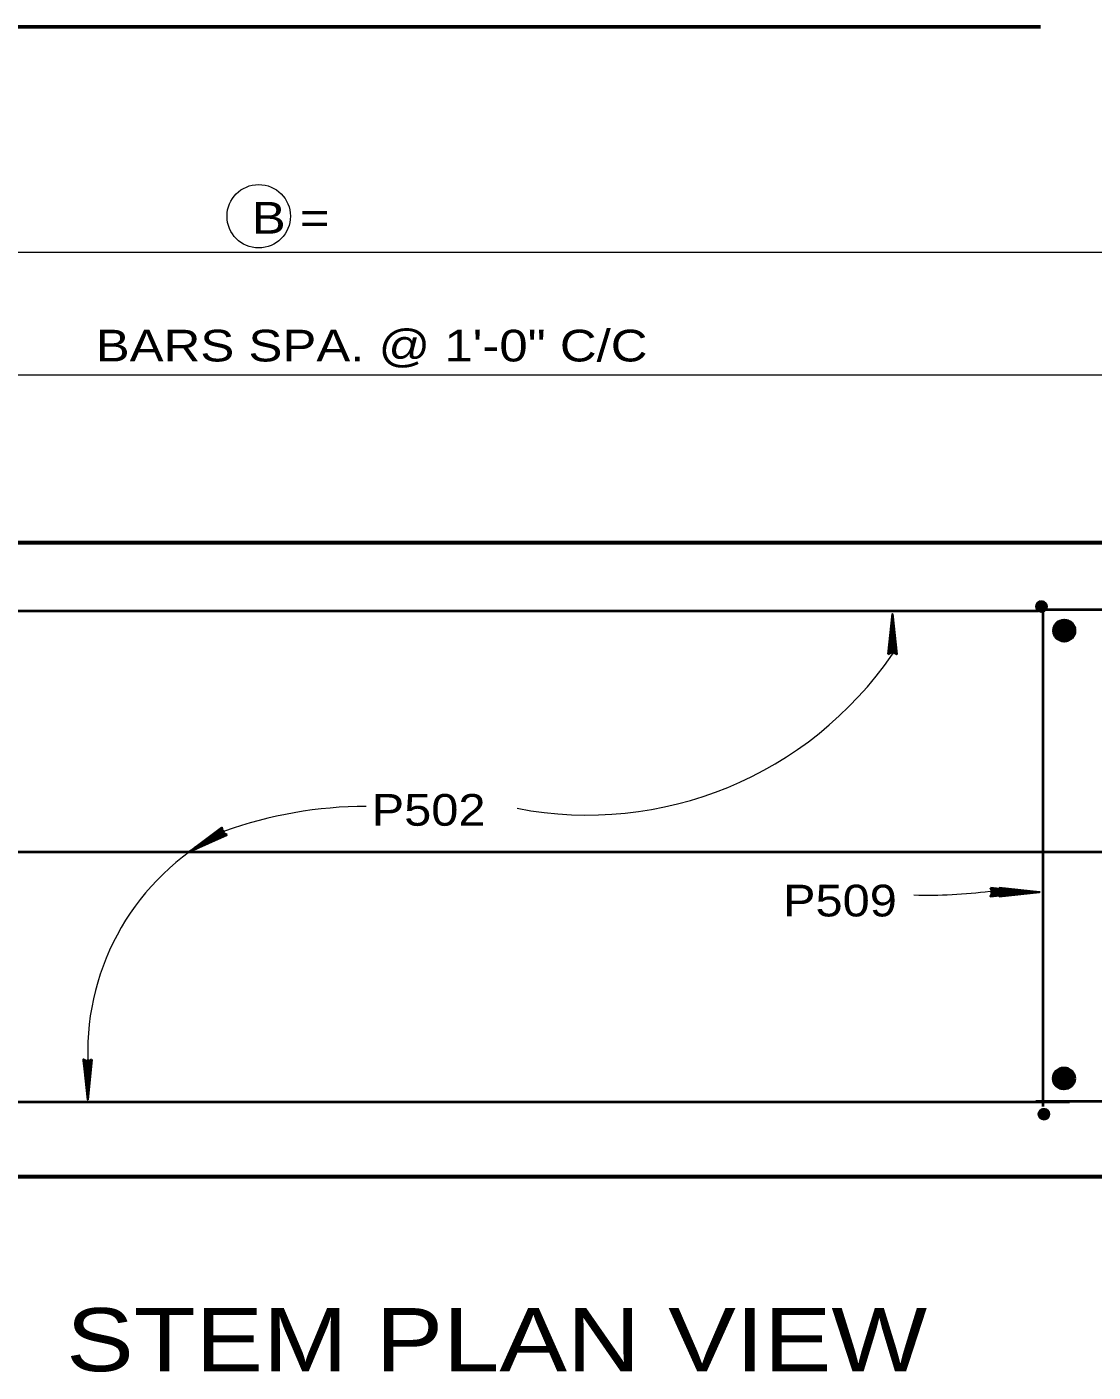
# Model space of a CAD drawing. Extents: x 4.49 to 7.69, y 0.28 to 2.27.
# Drawn here: x 5.0493 to 5.3295, y 1.2601 to 1.6136 of the extents above; entities that cross this region are included whole.
import ezdxf

# ---------------------------------------------------------------- set-up
doc = ezdxf.new("R2010")
doc.units = 0
doc.header["$LTSCALE"] = 0.0033
doc.layers.add('1', color=7, linetype='Continuous', lineweight=35)

msp = doc.modelspace()

# ---------------------------------------------------------------- linework, layer by layer
at = {"layer": '1', "lineweight": 53}
msp.add_line((5.043, 1.613583), (5.315667, 1.613583), dxfattribs=at)
at = {"layer": '1', "lineweight": 13}
for p, q in [((4.87325, 1.554417), (5.455583, 1.554417)), ((4.89, 1.522167), (5.436917, 1.522167))]:
    msp.add_line(p, q, dxfattribs=at)
at = {"layer": '1', "lineweight": 60}
for p, q in [((4.873333, 1.478083), (5.456667, 1.478083)), ((5.321667, 1.456417), (5.321833, 1.4535)), ((5.321833, 1.456417), (5.322083, 1.4535)), ((5.322083, 1.456417), (5.32225, 1.4535)), ((5.32225, 1.456417), (5.322417, 1.4535)), ((5.322417, 1.456417), (5.322583, 1.4535)), ((5.3225, 1.4565), (5.32275, 1.4535)), ((5.32275, 1.4565), (5.322917, 1.4535)), ((5.323, 1.4565), (5.323167, 1.4535)), ((5.323167, 1.4565), (5.323417, 1.4535)), ((5.323333, 1.4565), (5.3235, 1.4535)), ((5.3235, 1.4565), (5.32375, 1.453583)), ((5.32375, 1.4565), (5.323917, 1.453583)), ((5.319417, 1.454333), (5.319583, 1.456167)), ((5.319417, 1.454333), (5.324167, 1.453583)), ((5.319667, 1.45625), (5.319833, 1.453333)), ((5.319917, 1.45625), (5.320083, 1.453333)), ((5.320083, 1.45625), (5.320333, 1.453333)), ((5.32025, 1.45625), (5.320417, 1.453333)), ((5.320417, 1.45625), (5.320667, 1.453333)), ((5.320667, 1.456333), (5.320833, 1.453417)), ((5.32075, 1.456333), (5.320917, 1.453417)), ((5.320917, 1.456333), (5.321083, 1.453417)), ((5.321, 1.456333), (5.321167, 1.453417)), ((5.321167, 1.456333), (5.321417, 1.453417)), ((5.321417, 1.456333), (5.321667, 1.453417)), ((5.319333, 1.336667), (5.3195, 1.3385)), ((5.319333, 1.336667), (5.324083, 1.335917)), ((5.319583, 1.338583), (5.31975, 1.335667)), ((5.319833, 1.338583), (5.32, 1.335667)), ((5.32, 1.338583), (5.32025, 1.335667)), ((5.320167, 1.338583), (5.320333, 1.335667)), ((5.320333, 1.338583), (5.320583, 1.335667)), ((5.320583, 1.338667), (5.32075, 1.33575)), ((5.320667, 1.338667), (5.320833, 1.33575)), ((5.320833, 1.338667), (5.321, 1.33575)), ((5.320917, 1.338667), (5.321083, 1.33575)), ((5.321083, 1.338667), (5.321333, 1.33575)), ((5.321333, 1.338667), (5.321583, 1.33575)), ((5.321583, 1.33875), (5.32175, 1.335833)), ((5.32175, 1.33875), (5.322, 1.335833)), ((5.322, 1.33875), (5.322167, 1.335833)), ((5.322167, 1.33875), (5.322333, 1.335833)), ((5.322333, 1.33875), (5.3225, 1.335833)), ((5.322417, 1.338833), (5.322667, 1.335833)), ((5.322667, 1.338833), (5.322833, 1.335833)), ((5.322917, 1.338833), (5.323083, 1.335833)), ((5.323083, 1.338833), (5.323333, 1.335833)), ((5.32325, 1.338833), (5.323417, 1.335833)), ((5.323417, 1.338833), (5.323667, 1.335917)), ((5.323667, 1.338833), (5.323833, 1.335917))]:
    msp.add_line(p, q, dxfattribs=at)
at = {"layer": '1', "lineweight": 40}
for p, q in [((5.31475, 1.460667), (5.31675, 1.460333)), ((5.314833, 1.461167), (5.316833, 1.46075)), ((5.314833, 1.460917), (5.316833, 1.460583)), ((5.314833, 1.460833), (5.31675, 1.4605)), ((5.314833, 1.46075), (5.31675, 1.460417)), ((5.315, 1.462083), (5.314917, 1.460583)), ((5.314917, 1.461583), (5.316917, 1.46125)), ((5.314917, 1.4615), (5.316917, 1.461083)), ((5.314917, 1.461417), (5.316833, 1.461)), ((5.314917, 1.461333), (5.316833, 1.460917)), ((5.315083, 1.462083), (5.315, 1.460583)), ((5.315, 1.462083), (5.317, 1.46175)), ((5.315, 1.462), (5.317, 1.461667)), ((5.315, 1.461917), (5.317, 1.4615)), ((5.315, 1.461833), (5.317, 1.461417)), ((5.315, 1.461667), (5.316917, 1.461333)), ((5.315083, 1.46225), (5.317, 1.461917)), ((5.315167, 1.462083), (5.315083, 1.460583)), ((5.31525, 1.462083), (5.315167, 1.460583)), ((5.315167, 1.4605), (5.382333, 1.4605)), ((5.315333, 1.462083), (5.31525, 1.460583)), ((5.3155, 1.462083), (5.315417, 1.460583)), ((5.315583, 1.462083), (5.3155, 1.460583)), ((5.315667, 1.462083), (5.315583, 1.460583)), ((5.31575, 1.462083), (5.315667, 1.460583)), ((5.315833, 1.462083), (5.31575, 1.460583)), ((5.315917, 1.462083), (5.315833, 1.460583)), ((5.316, 1.462083), (5.315917, 1.460583)), ((5.316167, 1.462), (5.316, 1.4605)), ((5.316333, 1.462), (5.316167, 1.4605)), ((5.31625, 1.46125), (5.31625, 1.329917)), ((5.316417, 1.462), (5.316333, 1.4605)), ((5.316417, 1.462), (5.316333, 1.4605)), ((5.3165, 1.462), (5.316417, 1.4605)), ((5.316583, 1.462), (5.3165, 1.4605)), ((5.316667, 1.462), (5.316583, 1.4605)), ((5.31675, 1.462), (5.316667, 1.4605)), ((5.316833, 1.462), (5.31675, 1.4605)), ((5.316917, 1.462), (5.316833, 1.4605)), ((5.317083, 1.462), (5.317, 1.4605)), ((5.324, 1.4565), (5.319417, 1.454333)), ((5.319583, 1.456167), (5.320833, 1.457333)), ((5.323583, 1.456833), (5.31975, 1.456167)), ((5.323667, 1.4565), (5.31975, 1.455833)), ((5.321667, 1.456), (5.320333, 1.457)), ((5.323667, 1.456333), (5.31975, 1.455583)), ((5.32375, 1.456083), (5.319833, 1.455333)), ((5.32375, 1.455917), (5.319833, 1.455167)), ((5.319833, 1.453333), (5.323583, 1.452917)), ((5.32375, 1.455667), (5.319917, 1.454917)), ((5.323833, 1.4555), (5.32, 1.454833)), ((5.323833, 1.455333), (5.32, 1.454583)), ((5.323917, 1.455083), (5.320083, 1.454333)), ((5.323917, 1.454917), (5.320083, 1.454167)), ((5.324, 1.454667), (5.320083, 1.453917)), ((5.324083, 1.45425), (5.320167, 1.4535)), ((5.324083, 1.454083), (5.32025, 1.453333)), ((5.324083, 1.453833), (5.32025, 1.453167)), ((5.324167, 1.45375), (5.320333, 1.453)), ((5.324167, 1.453583), (5.320333, 1.452833)), ((5.323917, 1.338833), (5.319333, 1.336667)), ((5.3195, 1.3385), (5.32075, 1.339667)), ((5.3235, 1.339167), (5.319667, 1.3385)), ((5.323583, 1.338833), (5.319667, 1.338167)), ((5.323583, 1.338667), (5.319667, 1.337917)), ((5.323667, 1.338417), (5.31975, 1.337667)), ((5.323667, 1.33825), (5.31975, 1.3375)), ((5.323667, 1.338), (5.319833, 1.33725)), ((5.32375, 1.337833), (5.319917, 1.337167)), ((5.32375, 1.337667), (5.319917, 1.336917)), ((5.323833, 1.337417), (5.32, 1.336667)), ((5.323833, 1.33725), (5.32, 1.3365)), ((5.323917, 1.337), (5.32, 1.33625)), ((5.324, 1.336583), (5.320083, 1.335833)), ((5.324, 1.336417), (5.320167, 1.335667)), ((5.321583, 1.338333), (5.32025, 1.339333)), ((5.31975, 1.335667), (5.3235, 1.33525)), ((5.324, 1.336167), (5.320167, 1.3355)), ((5.324083, 1.336083), (5.32025, 1.335333)), ((5.324083, 1.335917), (5.32025, 1.335167)), ((5.314417, 1.33125), (5.382333, 1.33125)), ((5.315417, 1.32725), (5.317417, 1.326917)), ((5.3155, 1.32775), (5.3175, 1.327333)), ((5.3155, 1.3275), (5.3175, 1.327167)), ((5.3155, 1.327417), (5.317417, 1.327083)), ((5.3155, 1.327333), (5.317417, 1.327)), ((5.315667, 1.328667), (5.315583, 1.327167)), ((5.315583, 1.328167), (5.317583, 1.327833)), ((5.315583, 1.328083), (5.317583, 1.327667)), ((5.315583, 1.328), (5.3175, 1.327583)), ((5.315583, 1.327917), (5.3175, 1.3275)), ((5.31575, 1.328667), (5.315667, 1.327167)), ((5.315667, 1.328667), (5.317667, 1.328333)), ((5.315667, 1.328583), (5.317667, 1.32825)), ((5.315667, 1.3285), (5.317667, 1.328083)), ((5.315667, 1.328417), (5.317667, 1.328)), ((5.315667, 1.32825), (5.317583, 1.327917)), ((5.31575, 1.328833), (5.317667, 1.3285)), ((5.315833, 1.328667), (5.31575, 1.327167)), ((5.315917, 1.328667), (5.315833, 1.327167)), ((5.316, 1.328667), (5.315917, 1.327167)), ((5.316167, 1.328667), (5.316083, 1.327167)), ((5.31625, 1.328667), (5.316167, 1.327167)), ((5.316333, 1.328667), (5.31625, 1.327167)), ((5.316417, 1.328667), (5.316333, 1.327167)), ((5.3165, 1.328667), (5.316417, 1.327167)), ((5.316583, 1.328667), (5.3165, 1.327167)), ((5.316667, 1.328667), (5.316583, 1.327167)), ((5.316833, 1.328583), (5.316667, 1.327083)), ((5.317, 1.328583), (5.316833, 1.327083)), ((5.317083, 1.328583), (5.317, 1.327083)), ((5.317083, 1.328583), (5.317, 1.327083)), ((5.317167, 1.328583), (5.317083, 1.327083)), ((5.31725, 1.328583), (5.317167, 1.327083)), ((5.317333, 1.328583), (5.31725, 1.327083)), ((5.317417, 1.328583), (5.317333, 1.327083)), ((5.3175, 1.328583), (5.317417, 1.327083)), ((5.317583, 1.328583), (5.3175, 1.327083)), ((5.31775, 1.328583), (5.317667, 1.327083))]:
    msp.add_line(p, q, dxfattribs=at)
at = {"layer": '1'}
for p, q in [((5.27575, 1.449), (5.276667, 1.456833)), ((5.27575, 1.449), (5.276667, 1.456833)), ((5.275833, 1.449), (5.276667, 1.456833)), ((5.275917, 1.449), (5.27675, 1.456833)), ((5.275917, 1.449), (5.276917, 1.456833)), ((5.27675, 1.44875), (5.27675, 1.459333)), ((5.277417, 1.448917), (5.276667, 1.45625)), ((5.277583, 1.449), (5.27675, 1.456333)), ((5.277667, 1.449), (5.276917, 1.456333)), ((5.277833, 1.449), (5.277, 1.456333)), ((5.10125, 1.40225), (5.092167, 1.396917)), ((5.101417, 1.4015), (5.09425, 1.398083)), ((5.101417, 1.4015), (5.09425, 1.398333)), ((5.1015, 1.401417), (5.09425, 1.398083)), ((5.101667, 1.401167), (5.09425, 1.398083)), ((5.101667, 1.401167), (5.09425, 1.398083)), ((5.100583, 1.402917), (5.094583, 1.3985)), ((5.1005, 1.402917), (5.094667, 1.398667)), ((5.10075, 1.402917), (5.094833, 1.398417)), ((5.100917, 1.402667), (5.094833, 1.398417)), ((5.3025, 1.38625), (5.313083, 1.38625)), ((5.302667, 1.385583), (5.31, 1.386333)), ((5.30275, 1.38725), (5.310583, 1.386333)), ((5.30275, 1.38725), (5.310583, 1.386333)), ((5.30275, 1.387167), (5.310583, 1.386333)), ((5.30275, 1.387083), (5.310583, 1.38625)), ((5.30275, 1.387083), (5.310583, 1.386083)), ((5.30275, 1.385417), (5.310083, 1.38625)), ((5.30275, 1.385333), (5.310083, 1.386083)), ((5.30275, 1.385167), (5.310083, 1.386)), ((5.304833, 1.38625), (5.315417, 1.38625)), ((5.305, 1.385583), (5.312333, 1.386333)), ((5.305083, 1.38725), (5.312917, 1.386333)), ((5.305083, 1.38725), (5.312917, 1.386333)), ((5.305083, 1.387167), (5.312917, 1.386333)), ((5.305083, 1.387083), (5.312917, 1.38625)), ((5.305083, 1.387083), (5.312917, 1.386083)), ((5.305083, 1.385417), (5.312417, 1.38625)), ((5.305083, 1.385333), (5.312417, 1.386083)), ((5.305083, 1.385167), (5.312417, 1.386)), ((5.06425, 1.342), (5.065083, 1.334667)), ((5.064417, 1.342), (5.065167, 1.334667)), ((5.0645, 1.342), (5.065333, 1.334667)), ((5.064667, 1.342083), (5.065417, 1.33475)), ((5.066167, 1.342), (5.065167, 1.334167)), ((5.065333, 1.34225), (5.065333, 1.331667)), ((5.066167, 1.342), (5.065333, 1.334167)), ((5.066333, 1.342), (5.065417, 1.334167)), ((5.066333, 1.342), (5.065417, 1.334167)), ((5.06625, 1.342), (5.065417, 1.334167))]:
    msp.add_line(p, q, dxfattribs=at)
at = {"layer": '1', "lineweight": 60}
for points in [[(5.456667, 1.478083), (5.456667, 1.311417), (4.873333, 1.311417), (4.873333, 1.478083)], [(5.324583, 1.454833), (5.319417, 1.4555), (5.324, 1.4565)], [(5.320333, 1.452833), (5.320333, 1.457), (5.322, 1.452333), (5.3215, 1.4575), (5.323583, 1.452917), (5.322833, 1.457417), (5.32125, 1.452417), (5.324417, 1.45575), (5.319583, 1.456167), (5.322833, 1.4525), (5.320833, 1.457333), (5.324, 1.4565), (5.324167, 1.453583)], [(5.320833, 1.457333), (5.322083, 1.455167), (5.319833, 1.453333)], [(5.323583, 1.452917), (5.322083, 1.455167), (5.32425, 1.456083), (5.32225, 1.4575), (5.322083, 1.45525), (5.320417, 1.452917), (5.324417, 1.45525), (5.321667, 1.456)], [(5.32025, 1.335167), (5.32025, 1.339333), (5.321917, 1.334667), (5.321417, 1.339833), (5.3235, 1.33525), (5.32275, 1.33975), (5.321167, 1.33475), (5.324333, 1.338083), (5.3195, 1.3385), (5.32275, 1.334833), (5.32075, 1.339667), (5.323917, 1.338833), (5.324083, 1.335917)], [(5.3235, 1.33525), (5.322, 1.3375), (5.324167, 1.338417), (5.322167, 1.339833), (5.322, 1.337583), (5.320333, 1.33525), (5.324333, 1.337583), (5.321583, 1.338333)], [(5.3245, 1.337167), (5.319333, 1.337833), (5.323917, 1.338833)], [(5.32075, 1.339667), (5.322, 1.3375), (5.31975, 1.335667)]]:
    msp.add_lwpolyline(points, dxfattribs=at)
at = {"layer": '1', "lineweight": 40}
for points in [[(4.94275, 1.456), (4.95, 1.460167), (5.315167, 1.460167)], [(5.314583, 1.46125), (5.317167, 1.461583), (5.314833, 1.462083), (5.317167, 1.461), (5.31475, 1.460583), (5.31675, 1.46025), (5.31675, 1.462333), (5.315833, 1.46), (5.316083, 1.462583), (5.315083, 1.46025), (5.315417, 1.462583), (5.31625, 1.46), (5.314667, 1.46175), (5.317083, 1.461917), (5.315417, 1.460083), (5.3165, 1.4625), (5.314833, 1.462083), (5.31475, 1.460583), (5.315833, 1.46), (5.31675, 1.46025), (5.317167, 1.461), (5.317083, 1.461917), (5.3165, 1.4625), (5.315833, 1.461417), (5.317, 1.4605), (5.315083, 1.46025), (5.315833, 1.461417), (5.31475, 1.461917), (5.31575, 1.462583), (5.315833, 1.4615), (5.316667, 1.46025), (5.314667, 1.4615), (5.316, 1.461833), (5.31675, 1.462333)], [(5.324167, 1.453583), (5.322083, 1.452333), (5.320333, 1.452833), (5.319417, 1.454333)], [(4.893667, 1.396833), (5.314, 1.396833), (5.435333, 1.396833)], [(5.324083, 1.335917), (5.322, 1.334667), (5.32025, 1.335167), (5.319333, 1.336667)], [(4.894417, 1.33525), (4.941917, 1.33525), (4.949167, 1.331083), (5.323333, 1.331083)], [(5.31525, 1.327833), (5.317833, 1.328167), (5.3155, 1.328667), (5.317833, 1.327583), (5.315417, 1.327167), (5.317417, 1.326833), (5.317417, 1.328917), (5.3165, 1.326583), (5.31675, 1.329167), (5.31575, 1.326833), (5.316083, 1.329167), (5.316917, 1.326583), (5.315333, 1.328333), (5.31775, 1.3285), (5.316083, 1.326667), (5.317167, 1.329083), (5.3155, 1.328667), (5.315417, 1.327167), (5.3165, 1.326583), (5.317417, 1.326833), (5.317833, 1.327583), (5.31775, 1.3285), (5.317167, 1.329083), (5.3165, 1.328), (5.317667, 1.327083), (5.31575, 1.326833), (5.3165, 1.328), (5.315417, 1.3285), (5.316417, 1.329167), (5.3165, 1.328083), (5.317333, 1.326833), (5.315333, 1.328083), (5.316667, 1.328417), (5.317417, 1.328917)]]:
    msp.add_lwpolyline(points, dxfattribs=at)
at = {"layer": '1'}
for points in [[(5.275667, 1.44875), (5.27675, 1.459333), (5.277917, 1.44875), (5.27675, 1.449333)], [(5.276667, 1.4495), (5.276583, 1.454167), (5.276667, 1.454167), (5.276667, 1.45325), (5.276583, 1.4495), (5.2765, 1.4525), (5.276417, 1.449333), (5.276333, 1.451583), (5.27625, 1.449333), (5.2765, 1.452833), (5.276667, 1.4575), (5.276917, 1.456583), (5.276917, 1.457833), (5.276917, 1.4495), (5.277083, 1.451917), (5.277083, 1.449333), (5.276667, 1.454667), (5.277333, 1.449333)], [(5.101917, 1.40125), (5.092167, 1.396917), (5.100583, 1.403167), (5.100833, 1.401833)], [(5.10075, 1.401667), (5.096667, 1.399333), (5.096583, 1.399333), (5.0975, 1.399833), (5.100667, 1.401583), (5.098167, 1.400083), (5.100833, 1.401583), (5.099, 1.400333), (5.101083, 1.401333), (5.097917, 1.4), (5.093833, 1.397583), (5.094417, 1.398417), (5.093333, 1.397833), (5.100583, 1.402), (5.098417, 1.400833), (5.100583, 1.40225), (5.09625, 1.399167), (5.1005, 1.402417)], [(5.3025, 1.387333), (5.313083, 1.38625), (5.3025, 1.385083), (5.303083, 1.38625)], [(5.30325, 1.386333), (5.307917, 1.386417), (5.307917, 1.386333), (5.307, 1.386333), (5.30325, 1.386417), (5.30625, 1.3865), (5.303083, 1.386583), (5.305333, 1.386667), (5.303083, 1.38675), (5.306583, 1.3865), (5.31125, 1.386333), (5.310333, 1.386083), (5.311583, 1.386083), (5.30325, 1.386083), (5.305667, 1.385917), (5.303083, 1.385917), (5.308417, 1.386333), (5.303083, 1.385667)], [(5.304833, 1.387333), (5.315417, 1.38625), (5.304833, 1.385083), (5.305417, 1.38625)], [(5.305583, 1.386333), (5.31025, 1.386417), (5.31025, 1.386333), (5.309333, 1.386333), (5.305583, 1.386417), (5.308583, 1.3865), (5.305417, 1.386583), (5.307667, 1.386667), (5.305417, 1.38675), (5.308917, 1.3865), (5.313583, 1.386333), (5.312667, 1.386083), (5.313917, 1.386083), (5.305583, 1.386083), (5.308, 1.385917), (5.305417, 1.385917), (5.31075, 1.386333), (5.305417, 1.385667)], [(5.066417, 1.34225), (5.065333, 1.331667), (5.064167, 1.34225), (5.065333, 1.341667)], [(5.065417, 1.3415), (5.0655, 1.336833), (5.065417, 1.336833), (5.065417, 1.33775), (5.0655, 1.3415), (5.065583, 1.3385), (5.065667, 1.341667), (5.06575, 1.339417), (5.065833, 1.341667), (5.065583, 1.338167), (5.065417, 1.3335), (5.065167, 1.334417), (5.065167, 1.333167), (5.065167, 1.3415), (5.065, 1.339083), (5.065, 1.341667), (5.065417, 1.336333), (5.06475, 1.341667)]]:
    msp.add_lwpolyline(points, close=True, dxfattribs=at)
for points in [[(5.276667, 1.4495), (5.275917, 1.449083), (5.276167, 1.449333), (5.2765, 1.4495), (5.276417, 1.44975), (5.276083, 1.449583), (5.276833, 1.449417), (5.277333, 1.44925), (5.27775, 1.449)], [(5.10075, 1.401667), (5.101417, 1.4015), (5.101, 1.401417), (5.10075, 1.4015), (5.100583, 1.401333), (5.100917, 1.401167), (5.100667, 1.402), (5.1005, 1.4025), (5.1005, 1.402917)], [(5.30325, 1.386333), (5.302833, 1.387083), (5.303083, 1.386833), (5.30325, 1.3865), (5.3035, 1.386583), (5.303333, 1.386917), (5.303167, 1.386167), (5.303, 1.385667), (5.30275, 1.38525)], [(5.305583, 1.386333), (5.305167, 1.387083), (5.305417, 1.386833), (5.305583, 1.3865), (5.305833, 1.386583), (5.305667, 1.386917), (5.3055, 1.386167), (5.305333, 1.385667), (5.305083, 1.38525)], [(5.065417, 1.3415), (5.066167, 1.341917), (5.065917, 1.341667), (5.065583, 1.3415), (5.065667, 1.34125), (5.066, 1.341417), (5.06525, 1.341583), (5.06475, 1.34175), (5.064333, 1.342)]]:
    msp.add_lwpolyline(points, dxfattribs=at)
at = {"layer": '1', "lineweight": 13}
msp.add_circle((5.11025, 1.563833), 0.008333, dxfattribs=at)
at = {"layer": '1', "lineweight": 40}
for centre in [(5.315917, 1.4613), (5.316583, 1.327883)]:
    msp.add_circle(centre, 0.00132, dxfattribs=at)
at = {"layer": '1', "lineweight": 60}
for centre in [(5.321917, 1.454933), (5.321833, 1.337267)]:
    msp.add_circle(centre, 0.00264, dxfattribs=at)
at = {"layer": '1', "lineweight": 13}
for centre, radius, start, end in [((5.196638, 1.503522), 0.097046, 259.02789, 325.63978), ((5.13876, 1.297275), 0.111475, 90.13359, 109.66293), ((5.130445, 1.344181), 0.06514, 118.005, 181.69858), ((5.286423, 1.505864), 0.120431, 268.09338, 277.63143)]:
    msp.add_arc(centre, radius, start, end, dxfattribs=at)

# ---------------------------------------------------------------- texts
at = {"layer": '1'}
for s, height, width, p in [('B =      ', 0.008334, 1.2, (5.108417, 1.55925)), ('BARS SPA. @ 1\'-0" C/C', 0.008334, 1.2, (5.067417, 1.525667)), ('P502', 0.008334, 1.15, (5.139917, 1.403667)), ('P509', 0.008334, 1.15, (5.248, 1.379833)), ('STEM PLAN VIEW', 0.01658, 1.2, (5.059667, 1.260333))]:
    msp.add_text(s, height=height, dxfattribs=dict(at, width=width)).set_placement(p)

doc.saveas('drawing.dxf')
